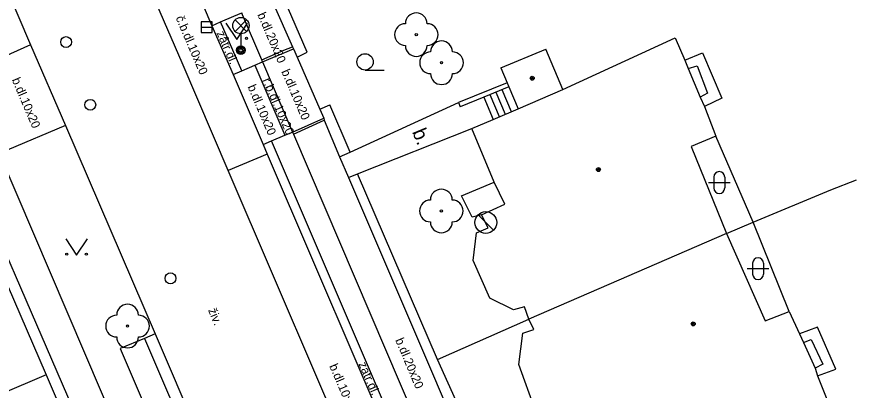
# Model space of a CAD drawing. Extents: x -600391 to -599491, y -1160176 to -1159402.
# Drawn here: x -599902.02 to -599863.62, y -1160146.21 to -1160129.08 of the extents above; entities that cross this region are included whole.
import ezdxf

# ---------------------------------------------------------------- set-up
doc = ezdxf.new("R2010")
doc.units = 0
for name, color, linetype in [('Level 10', 7, 'Continuous'), ('Level 11', 7, 'Continuous'), ('Level 22', 7, 'Continuous'), ('Level 27', 7, 'Continuous'), ('Level 28', 7, 'Continuous'), ('Level 33', 7, 'Continuous'), ('Level 36', 7, 'Continuous'), ('Level 39', 7, 'Continuous'), ('Level 40', 7, 'Continuous'), ('Level 5', 7, 'Continuous'), ('Level 51', 7, 'Continuous'), ('Level 7', 7, 'Continuous'), ('Level 8', 7, 'Continuous')]:
    doc.layers.add(name, color=color, linetype=linetype)

msp = doc.modelspace()

# ---------------------------------------------------------------- linework, layer by layer
at = {"layer": 'Level 10'}
for points in [[(-599900.25, -1160112.71), (-599895.14, -1160124.63), (-599894.96, -1160125.07), (-599894.75, -1160125.54), (-599893.06, -1160129.49), (-599892.08, -1160131.73), (-599890.71, -1160134.94), (-599890.53, -1160135.39), (-599884.33, -1160149.82), (-599881.2, -1160157.1), (-599880.97, -1160157.62), (-599879.19, -1160161.76), (-599879.01, -1160162.2)], [(-599903.64, -1160125.12), (-599901.38, -1160130.37), (-599899.78, -1160134.07), (-599895.66, -1160143.63), (-599891.79, -1160152.66), (-599890.19, -1160156.4), (-599887.83, -1160161.91), (-599887.42, -1160162.82), (-599885.04, -1160168.39), (-599884.65, -1160169.3), (-599882.88, -1160173.45)]]:
    msp.add_lwpolyline(points, dxfattribs=at)
at = {"layer": 'Level 11'}
for points in [[(-599880.3, -1160164.15), (-599880.98, -1160162.53), (-599882.98, -1160157.87), (-599886.11, -1160150.57), (-599892.31, -1160136.14), (-599894.43, -1160131.2), (-599896.75, -1160125.82), (-599902.04, -1160113.48), (-599906.68, -1160102.7), (-599908.55, -1160098.32), (-599910.62, -1160093.45), (-599915.66, -1160081.71)], [(-599901.38, -1160130.37), (-599904.01, -1160131.54), (-599904.38, -1160131.68), (-599904.42, -1160131.59), (-599906.62, -1160126.46), (-599906.66, -1160126.37)], [(-599892.67, -1160129.32), (-599892.05, -1160129.05), (-599891.69, -1160128.9)], [(-599890.73, -1160131.15), (-599890.77, -1160131.06), (-599891.65, -1160128.99), (-599891.69, -1160128.9)], [(-599893.06, -1160129.49), (-599892.67, -1160129.32)], [(-599891.69, -1160131.56), (-599892.67, -1160129.32)], [(-599890.77, -1160131.06), (-599889.76, -1160130.62), (-599889.36, -1160130.46)], [(-599890.73, -1160131.15), (-599889.32, -1160130.55)], [(-599891.69, -1160131.56), (-599891.09, -1160131.3), (-599890.73, -1160131.15)], [(-599891.09, -1160131.3), (-599889.71, -1160134.51)], [(-599890.73, -1160131.15), (-599889.36, -1160134.37)], [(-599892.08, -1160131.73), (-599891.69, -1160131.56)], [(-599880.03, -1160132.54), (-599879.6, -1160133.55)], [(-599879.75, -1160132.42), (-599879.32, -1160133.43)], [(-599880.58, -1160132.77), (-599880.15, -1160133.79)], [(-599880.3, -1160132.65), (-599879.87, -1160133.66)], [(-599886.71, -1160135.29), (-599881.74, -1160133.02)], [(-599889.36, -1160134.37), (-599887.93, -1160133.73)], [(-599899.78, -1160134.07), (-599902.46, -1160135.2), (-599902.82, -1160135.35)], [(-599889.32, -1160134.46), (-599887.9, -1160133.82)], [(-599890.33, -1160134.78), (-599889.71, -1160134.51), (-599889.36, -1160134.37)], [(-599889.36, -1160134.37), (-599889.32, -1160134.46), (-599882.98, -1160149.28), (-599879.7, -1160156.97), (-599879.66, -1160157.06)], [(-599886.38, -1160136.29), (-599881.13, -1160134.21)], [(-599890.71, -1160134.94), (-599890.33, -1160134.78)], [(-599880.57, -1160157.46), (-599880.81, -1160156.93), (-599883.94, -1160149.65), (-599890.33, -1160134.78)], [(-599902.82, -1160135.35), (-599902.78, -1160135.44), (-599896.61, -1160149.87)], [(-599890.53, -1160135.39), (-599892.31, -1160136.14)], [(-599880.68, -1160138.16), (-599881.12, -1160138.28), (-599881.6, -1160137.29), (-599880.11, -1160136.67)], [(-599895.66, -1160143.63), (-599896.16, -1160143.84), (-599897.27, -1160144.3)], [(-599896.16, -1160143.84), (-599891.58, -1160154.5), (-599891.26, -1160155.22), (-599890.66, -1160156.59)], [(-599897.27, -1160144.3), (-599895.16, -1160149.22), (-599896.61, -1160149.87)]]:
    msp.add_lwpolyline(points, dxfattribs=at)
at = {"layer": 'Level 22'}
for centre in [(-599883.68, -1160129.9), (-599882.52, -1160131.19), (-599882.53, -1160137.99), (-599896.93, -1160143.27)]:
    msp.add_circle(centre, 0.05, dxfattribs=at)
for centre, start, end in [((-599883.68, -1160129.4), 0, 180), ((-599884.18, -1160129.9), 90, 270), ((-599883.18, -1160129.9), 270, 90), ((-599882.52, -1160130.69), 0, 180), ((-599883.68, -1160130.4), 180, 0), ((-599883.02, -1160131.19), 90, 270), ((-599882.02, -1160131.19), 270, 90), ((-599882.52, -1160131.69), 180, 0), ((-599882.53, -1160137.49), 0, 180), ((-599883.03, -1160137.99), 90, 270), ((-599882.03, -1160137.99), 270, 90), ((-599882.53, -1160138.49), 180, 0), ((-599896.93, -1160142.77), 0, 180), ((-599897.43, -1160143.27), 90, 270), ((-599896.43, -1160143.27), 270, 90), ((-599896.93, -1160143.77), 180, 0)]:
    msp.add_arc(centre, 0.5, start, end, dxfattribs=at)
at = {"layer": 'Level 27'}
for p, q in [((-599893.55, -1160129.56), (-599893.05, -1160129.56)), ((-599880.137, -1160138.874), (-599880.844, -1160138.167))]:
    msp.add_line(p, q, dxfattribs=at)
msp.add_lwpolyline([(-599893.55, -1160129.81), (-599893.05, -1160129.81), (-599893.05, -1160129.31), (-599893.55, -1160129.31)], close=True, dxfattribs=at)
msp.add_circle((-599880.49, -1160138.52), 0.5, dxfattribs=at)
at = {"layer": 'Level 28'}
for centre in [(-599899.75, -1160130.24), (-599898.64, -1160133.12), (-599894.96, -1160141.08)]:
    msp.add_circle(centre, 0.25, dxfattribs=at)
at = {"layer": 'Level 33'}
for p, q in [((-599891.995, -1160129.75), (-599891.465, -1160129.22)), ((-599891.995, -1160129.22), (-599891.465, -1160129.75)), ((-599891.73, -1160129.86), (-599891.73, -1160130.61))]:
    msp.add_line(p, q, dxfattribs=at)
for centre, radius in [((-599891.73, -1160129.485), 0.375), ((-599891.73, -1160130.61), 0.2), ((-599891.73, -1160130.61), 0.145), ((-599891.73, -1160130.61), 0.0876)]:
    msp.add_circle(centre, radius, dxfattribs=at)
at = {"layer": 'Level 36'}
for p, q in [((-599886.03, -1160131.525), (-599885.155, -1160131.525)), ((-599870.026, -1160136.436), (-599870.026, -1160136.936)), ((-599869.526, -1160136.436), (-599869.526, -1160136.936)), ((-599870.276, -1160136.686), (-599869.276, -1160136.686)), ((-599868.496, -1160140.636), (-599867.496, -1160140.636)), ((-599868.246, -1160140.386), (-599868.246, -1160140.886)), ((-599867.746, -1160140.386), (-599867.746, -1160140.886))]:
    msp.add_line(p, q, dxfattribs=at)
for points in [[(-599892.42, -1160129.37), (-599891.92, -1160130.12), (-599891.42, -1160129.37)], [(-599899.77, -1160139.27), (-599899.27, -1160140.02), (-599898.77, -1160139.27)]]:
    msp.add_lwpolyline(points, dxfattribs=at)
for centre, radius in [((-599892.37, -1160130.07), 0.05), ((-599891.471, -1160130.07), 0.05), ((-599886.03, -1160131.15), 0.375), ((-599899.72, -1160139.97), 0.05), ((-599898.821, -1160139.97), 0.05)]:
    msp.add_circle(centre, radius, dxfattribs=at)
for centre, start, end in [((-599869.776, -1160136.436), 0, 180), ((-599869.776, -1160136.936), 180, 0), ((-599867.996, -1160140.386), 0, 180), ((-599867.996, -1160140.886), 180, 0)]:
    msp.add_arc(centre, 0.25, start, end, dxfattribs=at)
at = {"layer": 'Level 39'}
for centre, radius in [((-599878.36, -1160131.9), 0.09), ((-599878.36, -1160131.9), 0.0398), ((-599875.32, -1160136.09), 0.09), ((-599875.32, -1160136.09), 0.0398), ((-599870.97, -1160143.17), 0.09), ((-599870.97, -1160143.17), 0.0398)]:
    msp.add_circle(centre, radius, dxfattribs=at)
at = {"layer": 'Level 5'}
for points in [[(-599876.95, -1160132.42), (-599871.8, -1160130.05)], [(-599871.8, -1160130.05), (-599871.35, -1160131.07)], [(-599879.8, -1160131.43), (-599877.74, -1160130.56)], [(-599876.95, -1160132.42), (-599877.74, -1160130.56)], [(-599871.35, -1160131.07), (-599871.2, -1160131.45)], [(-599879.8, -1160131.43), (-599879.51, -1160132.11), (-599879.43, -1160132.3), (-599879.01, -1160133.3)], [(-599871.2, -1160131.45), (-599870.65, -1160132.77)], [(-599879.01, -1160133.3), (-599876.95, -1160132.42)], [(-599870.65, -1160132.77), (-599870.46, -1160133.19)], [(-599881.13, -1160134.21), (-599880.15, -1160133.79), (-599879.01, -1160133.3)], [(-599870.46, -1160133.19), (-599869.94, -1160134.56)], [(-599880.11, -1160136.67), (-599881.13, -1160134.21)], [(-599869.94, -1160134.56), (-599871.06, -1160135.04)], [(-599871.06, -1160135.04), (-599869.44, -1160139.03)], [(-599879.62, -1160137.68), (-599880.11, -1160136.67)], [(-599880.68, -1160138.16), (-599879.62, -1160137.68)], [(-599880.38, -1160138.76), (-599880.68, -1160138.16)], [(-599880.91, -1160139), (-599880.38, -1160138.76)], [(-599881.07, -1160140.26), (-599880.91, -1160139)], [(-599869.44, -1160139.03), (-599878.52, -1160142.95)], [(-599869.44, -1160139.03), (-599867.67, -1160143.03)], [(-599880.31, -1160141.99), (-599881.07, -1160140.26)], [(-599879.22, -1160142.53), (-599880.31, -1160141.99)], [(-599878.72, -1160142.38), (-599879.22, -1160142.53)], [(-599878.52, -1160142.95), (-599878.72, -1160142.38)], [(-599867.67, -1160143.03), (-599866.57, -1160142.6)], [(-599866.57, -1160142.6), (-599866.1, -1160143.63)], [(-599878.29, -1160143.42), (-599878.52, -1160142.95)], [(-599878.98, -1160145.04), (-599878.79, -1160143.6)], [(-599878.79, -1160143.6), (-599878.29, -1160143.42)], [(-599866.1, -1160143.63), (-599865.91, -1160144.02)], [(-599865.91, -1160144.02), (-599865.37, -1160145.2)], [(-599878.22, -1160147.11), (-599878.98, -1160145.04)], [(-599865.37, -1160145.2), (-599865.26, -1160145.55)], [(-599865.26, -1160145.55), (-599864.78, -1160146.78)]]:
    msp.add_lwpolyline(points, dxfattribs=at)
at = {"layer": 'Level 51'}
for points in [[(-599871.35, -1160131.07), (-599870.54, -1160130.74)], [(-599870.54, -1160130.74), (-599869.66, -1160132.81)], [(-599871.2, -1160131.45), (-599870.79, -1160131.33)], [(-599870.79, -1160131.33), (-599870.32, -1160132.59)], [(-599870.32, -1160132.59), (-599870.65, -1160132.77)], [(-599869.66, -1160132.81), (-599870.46, -1160133.19)], [(-599868.22, -1160138.5), (-599869.94, -1160134.56)], [(-599864.65, -1160137.02), (-599863.48, -1160136.56)], [(-599868.22, -1160138.5), (-599864.65, -1160137.02)], [(-599869.44, -1160139.03), (-599868.22, -1160138.5)], [(-599866.57, -1160142.6), (-599868.22, -1160138.5)], [(-599865.26, -1160143.32), (-599866.1, -1160143.63)], [(-599864.43, -1160145.24), (-599865.26, -1160143.32)], [(-599865.91, -1160144.02), (-599865.56, -1160143.88)], [(-599865.56, -1160143.88), (-599865.02, -1160145.02)], [(-599865.02, -1160145.02), (-599865.37, -1160145.2)], [(-599865.26, -1160145.55), (-599864.43, -1160145.24)]]:
    msp.add_lwpolyline(points, dxfattribs=at)
at = {"layer": 'Level 7'}
for points in [[(-599890.32, -1160128.3), (-599890.31, -1160128.33), (-599890.27, -1160128.42), (-599889.36, -1160130.46), (-599889.32, -1160130.55), (-599889.15, -1160130.93)], [(-599888.68, -1160130.71), (-599889.74, -1160128.26)], [(-599889.15, -1160130.93), (-599888.68, -1160130.71)], [(-599879.51, -1160132.11), (-599881.74, -1160133.02)], [(-599879.43, -1160132.3), (-599880.58, -1160132.77), (-599881.67, -1160133.21)], [(-599888.1, -1160133.32), (-599887.65, -1160133.12)], [(-599888.1, -1160133.32), (-599887.93, -1160133.73), (-599887.9, -1160133.82), (-599887.21, -1160135.5)], [(-599886.71, -1160135.29), (-599887.65, -1160133.12)], [(-599881.74, -1160133.02), (-599881.67, -1160133.21)], [(-599887.21, -1160135.5), (-599886.71, -1160135.29)], [(-599904.81, -1160135.91), (-599902.95, -1160140.23), (-599902.75, -1160140.69), (-599900.67, -1160145.51)], [(-599904.36, -1160135.72), (-599904.25, -1160135.96), (-599904.21, -1160136.06), (-599900.17, -1160145.36), (-599897.86, -1160150.69), (-599897.61, -1160151.26), (-599896.17, -1160154.58), (-599894.79, -1160157.8)], [(-599886.79, -1160136.46), (-599886.38, -1160136.29)], [(-599886.79, -1160136.46), (-599883.12, -1160145.01), (-599881.63, -1160148.49), (-599881.01, -1160149.81)], [(-599882.7, -1160144.81), (-599886.38, -1160136.29)], [(-599882.7, -1160144.81), (-599878.52, -1160142.95)], [(-599880.53, -1160149.62), (-599882.7, -1160144.81)], [(-599900.67, -1160145.51), (-599923.26, -1160155.15)], [(-599900.67, -1160145.51), (-599895.45, -1160157.67), (-599895.35, -1160157.9), (-599895.3, -1160158.03)]]:
    msp.add_lwpolyline(points, dxfattribs=at)
at = {"layer": 'Level 8'}
for points in [[(-599889.15, -1160130.93), (-599888.1, -1160133.32)], [(-599887.21, -1160135.5), (-599886.79, -1160136.46)]]:
    msp.add_lwpolyline(points, dxfattribs=at)

# ---------------------------------------------------------------- texts
at = {"layer": 'Level 40'}
for s, height, rotation, p in [('č.b.dl.10x20', 0.4, 293.1381, (-599894.73, -1160129.13)), ('b.dl.20x20', 0.4, 293.1377, (-599890.98, -1160128.98)), ('zatr.dl.', 0.4, 293.3292, (-599892.85, -1160129.83)), ('b.dl.10x20', 0.4, 293.1377, (-599889.88, -1160131.59)), ('b.dl.10x20', 0.4, 293.1381, (-599902.25, -1160131.97)), ('b.dl.10x20', 0.4, 293.1381, (-599891.43, -1160132.29)), ('r.b.dl.10x20', 0.39992, 293.657, (-599890.75, -1160131.99)), ('b.', 0.65, 292.5273, (-599883.88, -1160134.36)), ('živ.', 0.4, 292.3016, (-599893.24, -1160142.54)), ('b.dl.20x20', 0.4, 292.7805, (-599884.65, -1160143.91)), ('zatr.dl.', 0.4, 293.3292, (-599886.34, -1160145.01)), ('b.dl.10x20', 0.4, 293.1381, (-599887.68, -1160145.1))]:
    msp.add_text(s, height=height, rotation=rotation, dxfattribs=at).set_placement(p)

doc.saveas('drawing.dxf')
